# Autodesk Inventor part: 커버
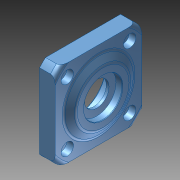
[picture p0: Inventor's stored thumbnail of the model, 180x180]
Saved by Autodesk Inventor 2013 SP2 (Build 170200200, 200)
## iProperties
Created: 2024-11
Part Number: 커버
Material: Generic
Document SubType Name: Modeling
Designer: a
Density: 1 g/cm^3
Author: a
변환 표준: STEP AP214IS
전처리기: Build: 200, Release: 2013 SP2 Update 6 - Date: Thu 07/17/2014
전송 단위: 밀리미터
불확실성: 0.01
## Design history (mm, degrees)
node "커버1"
node "솔리드1"
node "기준1"
